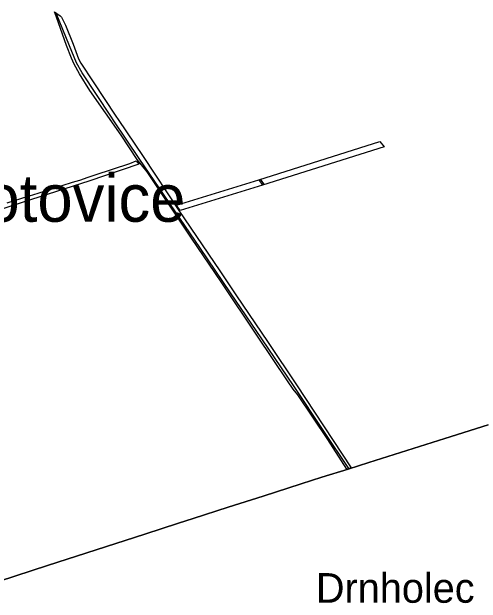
# Model space of a CAD drawing. Extents: x -616592 to -610527, y -1194438 to -1185930.
# Drawn here: x -613097 to -611515, y -1192397 to -1190402 of the extents above; entities that cross this region are included whole.
import ezdxf

# ---------------------------------------------------------------- set-up
doc = ezdxf.new("R2010")
doc.units = 0
for name, color, linetype in [('LES_ZV', 7, 'Continuous'), ('Level 255', 7, 'Continuous'), ('OVNE_PRE', 7, 'Continuous')]:
    doc.layers.add(name, color=color, linetype=linetype)

msp = doc.modelspace()

# ---------------------------------------------------------------- linework, layer by layer
at = {"layer": 'LES_ZV'}
for points in [[(-612953.4, -1190402.4), (-612933.9, -1190415.8), (-612929.7, -1190420.5), (-612916.8, -1190447.4), (-612890.8, -1190510.9), (-612873.1, -1190561.1), (-612865.2, -1190575.9), (-612823.4, -1190638.7), (-612746.2, -1190754.3), (-612738.8, -1190765.6), (-612654.5, -1190890.1), (-612534.3, -1191072.9), (-612396.1, -1191275.7), (-612342.5, -1191356.4), (-612233.4, -1191518), (-612137.9, -1191660), (-611953, -1191940.4), (-611967.2, -1191944.8), (-612032.2, -1191844.7), (-612133.4, -1191693.7), (-612148.4, -1191674.6), (-612167.4, -1191647.3), (-612269.4, -1191496.8), (-612392, -1191313.1), (-612491, -1191165.9), (-612641, -1190941.7), (-612674.6, -1190900.6), (-612728.6, -1190818), (-612833.8, -1190667.4), (-612868.9, -1190611.8), (-612886.9, -1190578.8), (-612896.3, -1190558.7), (-612913.1, -1190515.9), (-612947.2, -1190420.3), (-612953.4, -1190402.4)], [(-612542.6, -1191054.6), (-612263.9, -1190969.2), (-611856.6, -1190839.4), (-611842.3, -1190857.4), (-612251.9, -1190987.3), (-612530.1, -1191072.5), (-612542.6, -1191054.6)], [(-613112.6, -1191046.6), (-613041.8, -1191024.1), (-613027, -1191020.1), (-612962.4, -1190999.2), (-612893.1, -1190976.7), (-612867.6, -1190969.7), (-612839.7, -1190960), (-612816.7, -1190951.9), (-612700, -1190913.6), (-612677.7, -1190905.3), (-612669.6, -1190916.7), (-612837.8, -1190973.5), (-613031.5, -1191035.1), (-613229.8, -1191098.9)]]:
    msp.add_lwpolyline(points, dxfattribs=at)
at = {"layer": 'Level 255'}
for p, q in [((-612263.9, -1190969.2), (-612251.9, -1190987.3)), ((-612258.9, -1190967.5), (-612246.9, -1190985.8))]:
    msp.add_line(p, q, dxfattribs=at)
for points in [[(-611961.3, -1191942.9), (-612045.4, -1191816.2), (-612145.1, -1191666), (-612254.3, -1191505.4), (-612359.6, -1191350.3), (-612461.2, -1191200.9), (-612564.7, -1191048.6), (-612667.6, -1190897.1), (-612753, -1190769.8), (-612763.3, -1190754.5), (-612859.8, -1190607.6), (-612879, -1190574.9), (-612903.3, -1190517.1), (-612947.5, -1190406.5)], [(-611490.7, -1191795.5), (-611637.2, -1191841.5), (-611765.2, -1191881.9), (-611893.1, -1191922.4), (-611963.7, -1191944.7), (-612051.8, -1191972), (-612121.6, -1191994.4), (-612250.1, -1192036.1), (-612367.8, -1192073.4), (-612485.5, -1192110.8), (-612535.5, -1192126.9), (-612649.3, -1192163.7), (-612813.1, -1192216.6), (-612976.8, -1192269.4), (-613140.6, -1192322.3)], [(-611490.7, -1191795.5), (-611637.2, -1191841.5), (-611765.2, -1191881.9), (-611893.1, -1191922.4), (-611963.7, -1191944.7), (-612051.8, -1191972), (-612121.6, -1191994.4), (-612250.1, -1192036.1), (-612367.8, -1192073.4), (-612485.5, -1192110.8), (-612535.5, -1192126.9), (-612649.3, -1192163.7), (-612813.1, -1192216.6), (-612976.8, -1192269.4), (-613140.6, -1192322.3)]]:
    msp.add_lwpolyline(points, dxfattribs=at)
at = {"layer": 'OVNE_PRE'}
msp.add_lwpolyline([(-613140.6, -1192322.3), (-612976.8, -1192269.4), (-612813.1, -1192216.6), (-612649.3, -1192163.7), (-612535.5, -1192126.9), (-612485.5, -1192110.8), (-612367.8, -1192073.4), (-612250.1, -1192036.1), (-612121.6, -1191994.4), (-612051.8, -1191972), (-611963.7, -1191944.7), (-611893.1, -1191922.4), (-611765.2, -1191881.9), (-611637.2, -1191841.5), (-611490.7, -1191795.5)], dxfattribs=at)

# ---------------------------------------------------------------- texts
at = {"layer": 'Level 255'}
for s, height, p in [('Troskotovice', 160, (-613724.6, -1191110.4)), ('Drnholec', 100, (-612072, -1192395.4))]:
    msp.add_text(s, height=height, dxfattribs=at).set_placement(p)

doc.saveas('drawing.dxf')
